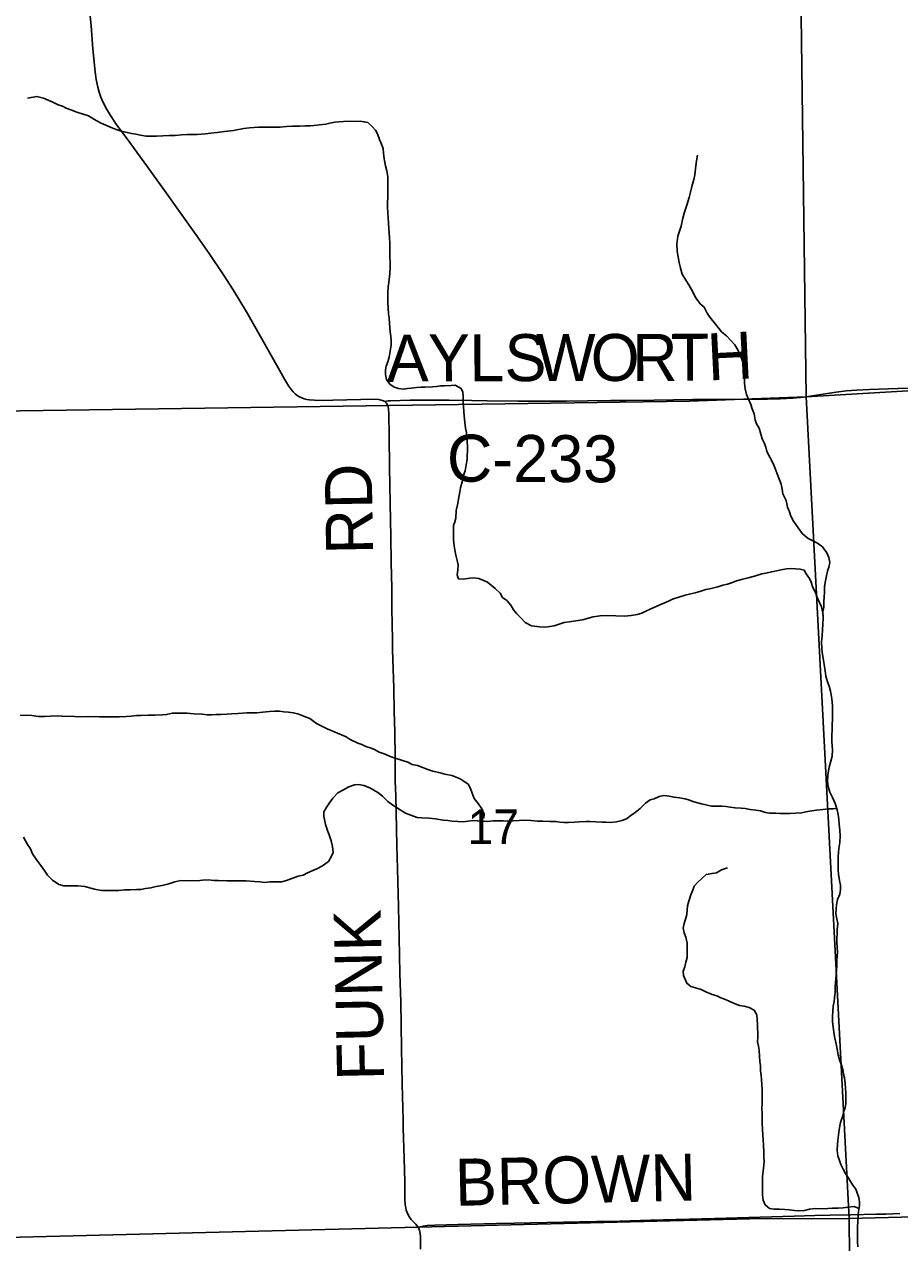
# Model space of a CAD drawing. Extents: x 1985906 to 2360102, y 891258 to 1222054.
# Drawn here: x 2081902 to 2087486, y 977355 to 985131 of the extents above; entities that cross this region are included whole.
import ezdxf

# ---------------------------------------------------------------- set-up
doc = ezdxf.new("R2010")
doc.units = 0
for name, color, linetype in [('GM_X_County_Road', 7, 'Continuous'), ('GM_X_County_Road_Text', 7, 'Continuous'), ('GM_X_Minor_River', 7, 'Continuous'), ('GM_X_Section', 7, 'Continuous'), ('GM_X_Section_Text', 7, 'Continuous'), ('GM_X_Township_Road', 7, 'Continuous'), ('GM_X_Township_Road_Text', 7, 'Continuous')]:
    doc.layers.add(name, color=color, linetype=linetype)

msp = doc.modelspace()

# ---------------------------------------------------------------- linework, layer by layer
at = {"layer": 'GM_X_County_Road'}
for points in [[(2084201.4, 982723), (2084193.3, 982727.4), (2084179.3, 982733), (2084163.9, 982736.4), (2084131.6, 982738.5), (2084049.5, 982737), (2083869.4, 982731.1), (2083803.2, 982729.7), (2083753.8, 982731.1), (2083720.6, 982734), (2083704.2, 982736.8), (2083688, 982740.9), (2083672.2, 982746.6), (2083657.1, 982753.9), (2083642.8, 982762.7), (2083629.6, 982773.1), (2083617.6, 982784.7), (2083606.6, 982797.3), (2083587.3, 982824.3), (2083561.9, 982866.8), (2083529.5, 982924), (2083409.4, 983138.8), (2083319.4, 983295.1), (2083234.8, 983435.5), (2083173.1, 983532.1), (2083081, 983667.9), (2082996.3, 983788.8), (2082796.1, 984069.4), (2082681.3, 984229.4), (2082575.7, 984375.7), (2082487.4, 984494.3), (2082450.8, 984549), (2082425.4, 984591.6), (2082402.8, 984635.7), (2082389.9, 984666.1), (2082379.1, 984697.4), (2082370.3, 984729.3), (2082360.3, 984777.8), (2082353.4, 984826.8), (2082339.9, 984973.9), (2082327.7, 985121.1), (2082314.6, 985268.1)], [(2084201.4, 982723), (2084213.1, 982725.9), (2084223.4, 982727.6), (2084238.8, 982728.8), (2084363.4, 982733), (2084609.5, 982732.8), (2084757.2, 982729.6), (2084855.5, 982728.1), (2085051.9, 982725.8), (2085133.9, 982724.8), (2085265.1, 982724.7), (2085363.5, 982725.4), (2085493.8, 982727), (2085641.7, 982729.2), (2085740, 982730.4), (2085920.5, 982732), (2086166.6, 982735.9), (2086363.4, 982736.6), (2086560.3, 982738.3), (2086642.3, 982739.2), (2086724, 982741), (2086805.4, 982745), (2086854.1, 982749.4), (2086902.7, 982756), (2086983.3, 982769.3), (2087080.5, 982783.8), (2087145.9, 982790.7), (2087211.4, 982795.1), (2087293.4, 982799.3), (2087473.6, 982805.7), (2087555.6, 982808.2)], [(2084414.3, 977451.2), (2084409.8, 977459), (2084398.7, 977472.5), (2084380.7, 977491), (2084369.8, 977503.5), (2084359.7, 977517), (2084350.9, 977531.5), (2084343.7, 977546.7), (2084338.4, 977562.7), (2084334.7, 977579), (2084332.3, 977595.6), (2084330.3, 977628.8), (2084328.8, 977743.9), (2084324.6, 977891.5), (2084319.7, 978088.1), (2084318.3, 978137.3), (2084311.7, 978366.9), (2084307.9, 978596.7), (2084303.1, 978892), (2084298.1, 979072.5), (2084293, 979302.1), (2084288.1, 979499), (2084284.2, 979662.9), (2084278.9, 979892.6), (2084276.1, 979990.9), (2084274.2, 980105.7), (2084272.2, 980204.1), (2084268.5, 980302.6), (2084267.6, 980450.4), (2084265.8, 980614.4), (2084262, 980745.6), (2084258.4, 980893.1), (2084251.2, 981138.8), (2084249.8, 981204.4), (2084247, 981401.2), (2084246, 981532.5), (2084243.1, 981696.5), (2084240.1, 981860.6), (2084236.4, 982073.9), (2084231.9, 982303.6), (2084229.1, 982500.5), (2084227.3, 982648.2), (2084225.6, 982671.1), (2084224.2, 982679.4), (2084222.7, 982687.4), (2084220.2, 982696.8), (2084216.4, 982705.6), (2084211.7, 982712.9), (2084205.6, 982719.4), (2084201.4, 982723)], [(2084429.7, 977312.3), (2084429.7, 977376.9), (2084428.9, 977396), (2084427.4, 977411.2), (2084424.1, 977427.1), (2084417.8, 977444.6), (2084414.3, 977451.2)]]:
    msp.add_lwpolyline(points, dxfattribs=at)
at = {"layer": 'GM_X_Minor_River'}
for points in [[(2081921.8, 984659.3), (2081982.2, 984671.3), (2082024.6, 984659.2), (2082054.8, 984647.1), (2082083.1, 984633.1), (2082117.4, 984617), (2082145.6, 984608.9), (2082169.8, 984596.9), (2082198, 984584.8), (2082236.4, 984570.7), (2082276.7, 984556.7), (2082311, 984546.6), (2082361.4, 984516.5), (2082391.7, 984500.4), (2082421.9, 984486.3), (2082456.2, 984472.2), (2082488.5, 984460.2), (2082520.8, 984450.1), (2082585.3, 984434), (2082613.5, 984430), (2082643.7, 984423.9), (2082680, 984417.9), (2082744.5, 984417.9), (2082825.1, 984421.8), (2082865.4, 984421.8), (2082905.7, 984425.8), (2082941.9, 984427.8), (2083004.4, 984427.8), (2083030.6, 984429.7), (2083058.8, 984431.7), (2083091, 984435.7), (2083131.3, 984439.7), (2083179.7, 984447.7), (2083236.1, 984453.7), (2083302.5, 984465.7), (2083338.8, 984469.7), (2083395.2, 984473.7), (2083534.2, 984473.6), (2083574.5, 984479.6), (2083612.8, 984481.6), (2083657.1, 984481.6), (2083693.4, 984483.6), (2083725.6, 984483.6), (2083749.8, 984485.6), (2083784.1, 984489.6), (2083824.4, 984493.5), (2083850.5, 984499.6), (2083882.8, 984505.6), (2083908.9, 984509.6), (2083937.2, 984511.6), (2083985.5, 984513.5), (2084017.7, 984511.5), (2084043.9, 984513.5), (2084068.1, 984509.5), (2084094.3, 984503.4), (2084120.6, 984479.3), (2084142.8, 984455.2), (2084155, 984431.1), (2084167.1, 984395), (2084181.3, 984366.8), (2084191.4, 984338.7), (2084193.5, 984308.6), (2084197.6, 984272.5), (2084205.8, 984228.3), (2084213.9, 984196.2), (2084220.1, 984158), (2084220.2, 984095.8), (2084220.3, 984065.7), (2084220.4, 984029.5), (2084218.5, 983989.4), (2084218.5, 983965.3), (2084220.6, 983923.1), (2084222.7, 983899), (2084224.8, 983858.9), (2084231.1, 983768.5), (2084233.2, 983734.4), (2084233.4, 983644), (2084235.5, 983615.9), (2084235.6, 983575.8), (2084233.6, 983539.6), (2084227.7, 983483.4), (2084223.8, 983455.3), (2084221.8, 983419.2), (2084221.9, 983389), (2084220, 983354.9), (2084222.1, 983318.8), (2084226.2, 983282.6), (2084230.3, 983258.5), (2084232.4, 983222.4), (2084234.4, 983194.3), (2084236.5, 983168.2), (2084240.6, 983138.1), (2084242.7, 983109.9), (2084242.8, 983083.8), (2084236.8, 983045.7), (2084228.8, 983005.6), (2084220.8, 982977.4), (2084210.8, 982949.3), (2084206.9, 982925.3), (2084206.9, 982895.1), (2084213.1, 982863)], [(2086997.1, 981345.5), (2086995.2, 981381.7), (2087001.2, 981411.8), (2087003.1, 981441.9), (2087005.1, 981478.1), (2087007, 981504.2), (2087006.9, 981542.3), (2087012.9, 981578.4), (2087018.9, 981610.6), (2087024.9, 981640.7), (2087034.9, 981666.8), (2087040.8, 981696.9), (2087034.7, 981729), (2087020.5, 981757.1), (2086994.3, 981795.3), (2086962, 981819.4), (2086931.7, 981833.5), (2086901.4, 981849.5), (2086867.1, 981879.7), (2086838.8, 981917.8), (2086808.5, 981960), (2086792.3, 981992.2), (2086782.2, 982020.3), (2086770, 982048.4), (2086761.8, 982092.6), (2086741.6, 982134.8), (2086735.5, 982164.9), (2086729.4, 982197), (2086719.2, 982223.1), (2086705, 982261.3), (2086690.8, 982295.4), (2086678.7, 982327.5), (2086658.4, 982367.7), (2086638.2, 982403.8), (2086632.1, 982432), (2086621.9, 982460.1), (2086609.8, 982486.2), (2086599.7, 982514.3), (2086589.5, 982552.4), (2086573.3, 982580.6), (2086565.2, 982606.7), (2086557, 982644.8), (2086544.9, 982676.9), (2086536.7, 982705.1), (2086520.5, 982743.2), (2086508.4, 982769.3), (2086500.2, 982803.5), (2086496.1, 982841.6), (2086496, 982883.8), (2086493.9, 982923.9), (2086487.8, 982968.1), (2086479.6, 982994.2), (2086465.5, 983022.3), (2086455.3, 983048.4), (2086435.1, 983084.6), (2086410.9, 983110.7), (2086380.6, 983142.8), (2086350.3, 983169), (2086311.9, 983217.2), (2086275.5, 983261.4), (2086257.3, 983287.5), (2086239.1, 983325.6), (2086212.8, 983347.7), (2086186.5, 983385.9), (2086158.2, 983438.1), (2086142, 983468.2), (2086121.8, 983498.4), (2086099.5, 983536.5), (2086087.4, 983574.7), (2086079.2, 983610.8), (2086071, 983657), (2086067, 983683.1), (2086064.8, 983727.3), (2086070.8, 983779.5), (2086092.8, 983843.7), (2086102.7, 983893.9), (2086110.7, 983926), (2086128.7, 983976.2), (2086142.7, 984026.4), (2086150.7, 984060.5), (2086160.7, 984096.7), (2086172.7, 984140.8), (2086178.6, 984170.9), (2086186.6, 984227.2), (2086190.5, 984259.3), (2086196.5, 984295.4)], [(2084213.1, 982863), (2084233.3, 982834.9), (2084261.5, 982814.8), (2084289.8, 982806.8), (2084320, 982802.7), (2084346.2, 982806.7), (2084370.4, 982808.7), (2084404.6, 982812.7), (2084430.8, 982814.7), (2084457, 982814.7), (2084505.3, 982816.7), (2084531.5, 982818.7), (2084557.7, 982822.7), (2084581.9, 982822.6), (2084624.2, 982826.6), (2084650.4, 982828.6), (2084688.7, 982806.5), (2084698.9, 982782.4), (2084700.9, 982756.3), (2084701, 982724.2), (2084705.2, 982659.9), (2084707.3, 982631.8), (2084711.4, 982591.7), (2084715.5, 982553.5), (2084723.7, 982525.4), (2084725.7, 982497.3), (2084727.8, 982463.2), (2084729.9, 982439.1), (2084730, 982411), (2084728, 982376.8), (2084726.1, 982352.8), (2084720.1, 982318.6), (2084714.1, 982280.5), (2084702.1, 982246.3), (2084694.2, 982210.2), (2084684.2, 982172.1), (2084680.2, 982148), (2084676.2, 982123.9), (2084666.3, 982063.7), (2084656.3, 982027.5), (2084654.4, 981979.3), (2084648.4, 981955.2), (2084640.4, 981931.2), (2084640.6, 981840.8), (2084644.7, 981802.7), (2084648.8, 981776.6), (2084655, 981742.4), (2084663.1, 981708.3), (2084669.2, 981682.2), (2084667.3, 981648), (2084663.3, 981617.9), (2084671.4, 981591.8), (2084703.7, 981589.8), (2084744, 981595.8), (2084768.1, 981597.8), (2084800.4, 981593.8), (2084826.6, 981583.7), (2084856.9, 981569.7), (2084905.3, 981529.5), (2084937.6, 981499.3), (2084951.8, 981473.2), (2084980, 981453.1), (2085006.3, 981423), (2085022.5, 981394.9), (2085044.7, 981368.8), (2085069, 981342.7), (2085097.2, 981312.5), (2085137.6, 981292.4), (2085188, 981286.4), (2085218.2, 981284.3), (2085242.4, 981286.3), (2085282.7, 981292.3), (2085312.9, 981302.3), (2085345.1, 981312.4), (2085377.3, 981316.4), (2085461.9, 981330.4), (2085530.4, 981348.4), (2085574.7, 981356.4), (2085623.1, 981358.4), (2085675.4, 981356.4), (2085729.9, 981354.3), (2085774.2, 981358.3), (2085810.4, 981364.3), (2085840.6, 981372.3), (2085866.8, 981386.4), (2085895, 981398.4), (2085955.4, 981426.5), (2085981.5, 981436.5), (2086011.7, 981448.5), (2086035.9, 981462.6), (2086076.2, 981474.6), (2086118.5, 981486.6), (2086144.6, 981494.6), (2086180.9, 981502.6), (2086217.1, 981512.7), (2086249.3, 981522.7), (2086275.5, 981528.7), (2086325.9, 981540.7), (2086358.1, 981550.7), (2086388.3, 981558.7), (2086418.5, 981568.8)], [(2086418.5, 981568.8), (2086444.7, 981578.8), (2086484.9, 981588.8), (2086519.2, 981598.8), (2086559.4, 981608.8), (2086605.8, 981622.8), (2086642, 981630.9), (2086670.2, 981636.9), (2086730.6, 981648.9), (2086764.9, 981654.9), (2086797.1, 981656.9), (2086821.3, 981654.8), (2086851.5, 981652.8), (2086877.7, 981646.8), (2086889.9, 981622.7), (2086910.1, 981594.6), (2086922.2, 981570.5), (2086932.4, 981536.3), (2086948.6, 981504.2), (2086956.7, 981478.1), (2086972.9, 981446), (2086987.1, 981413.8), (2086995.2, 981375.7), (2086997.3, 981341.5), (2086995.4, 981301.4), (2086991.6, 981229.1), (2086987.6, 981186.9), (2086989.7, 981146.8), (2086991.8, 981120.7), (2087000, 981072.5), (2087006.1, 981030.3), (2087010.2, 981004.2), (2087014.3, 980970.1), (2087026.5, 980933.9), (2087036.6, 980905.8), (2087044.8, 980875.7), (2087050.9, 980841.6), (2087055, 980807.4), (2087057.1, 980779.3), (2087057.3, 980697), (2087055.4, 980658.9), (2087055.4, 980634.8), (2087053.5, 980588.6), (2087053.6, 980552.5), (2087057.7, 980500.3), (2087055.8, 980460.1), (2087045.8, 980428), (2087035.8, 980389.8), (2087031.9, 980365.8), (2087027.9, 980337.7), (2087026, 980297.5), (2087030.1, 980265.4), (2087040.2, 980229.2), (2087056.4, 980197.1), (2087074.6, 980156.9), (2087086.8, 980116.8), (2087092.9, 980086.7), (2087097.1, 980056.5), (2087099.1, 980026.4), (2087103.3, 979988.3), (2087105.4, 979952.1), (2087103.4, 979907.9), (2087097.5, 979869.8), (2087093.6, 979819.6), (2087093.8, 979731.3), (2087095.8, 979707.2), (2087102, 979667), (2087108.1, 979636.9), (2087108.2, 979608.8), (2087104.2, 979578.7), (2087090.2, 979544.6), (2087082.2, 979510.4), (2087080.2, 979486.3), (2087078.3, 979454.2), (2087084.4, 979422.1), (2087090.5, 979392), (2087086.6, 979353.8), (2087086.7, 979325.7), (2087084.7, 979299.6), (2087084.8, 979271.5), (2087086.9, 979239.4), (2087088.9, 979209.3), (2087087, 979185.2), (2087085, 979155.1), (2087085.1, 979120.9), (2087083.2, 979094.8), (2087081.2, 979064.7), (2087079.3, 979038.6), (2087075.3, 978990.4), (2087073.4, 978954.3), (2087069.5, 978918.2), (2087067.5, 978894.1), (2087061.5, 978864), (2087059.6, 978831.8), (2087057.7, 978797.7), (2087057.7, 978765.6), (2087061.8, 978729.4), (2087068, 978683.3), (2087072.1, 978659.2), (2087080.2, 978623), (2087086.3, 978590.9)], [(2081876.6, 980720), (2081912.9, 980722), (2081949.2, 980720), (2081991.5, 980714), (2082033.8, 980713.9), (2082070.1, 980715.9), (2082112.4, 980717.9), (2082140.6, 980715.9), (2082223.2, 980713.8), (2082261.5, 980711.8), (2082320, 980713.8), (2082382.4, 980711.7), (2082507.4, 980711.7), (2082553.7, 980713.7), (2082583.9, 980715.6), (2082618.2, 980719.6), (2082644.4, 980719.6), (2082692.7, 980721.6), (2082735, 980721.6), (2082783.4, 980723.6), (2082809.6, 980725.5), (2082845.8, 980733.6), (2082872, 980733.5), (2082940.5, 980733.5), (2082982.8, 980729.5), (2083037.3, 980727.4), (2083067.5, 980723.4), (2083095.7, 980723.4), (2083123.9, 980725.4), (2083156.2, 980725.4), (2083194.4, 980727.3), (2083224.6, 980729.3), (2083264.9, 980733.3), (2083321.4, 980737.3), (2083385.8, 980737.3), (2083424.1, 980741.3), (2083466.4, 980745.3), (2083500.7, 980747.2), (2083530.9, 980747.2), (2083557.1, 980743.2), (2083587.3, 980741.2), (2083617.6, 980737.1), (2083645.8, 980731.1), (2083690.1, 980713), (2083722.4, 980700.9), (2083766.8, 980668.8), (2083833.4, 980634.6), (2083885.8, 980612.5), (2083954.4, 980584.4), (2083980.6, 980566.3), (2084029.1, 980542.2), (2084055.3, 980534.1), (2084081.5, 980522), (2084107.7, 980514), (2084136, 980501.9), (2084166.2, 980485.9), (2084204.5, 980471.8), (2084236.8, 980457.7), (2084275.1, 980445.6), (2084347.7, 980421.5), (2084376, 980407.4), (2084410.2, 980399.4), (2084476.8, 980375.3), (2084507, 980365.2), (2084555.4, 980353.1), (2084583.7, 980345.1), (2084630, 980337), (2084678.4, 980316.9), (2084706.7, 980300.8), (2084732.9, 980280.8), (2084749.1, 980252.6), (2084759.2, 980224.5), (2084771.4, 980190.4), (2084797.7, 980158.2), (2084819.9, 980124.1), (2084836.1, 980090), (2084834.2, 980063.8)], [(2087084, 980126.1), (2087062.6, 980124.8), (2087032.4, 980122.8), (2086996.2, 980118.8), (2086955.9, 980114.8), (2086925.6, 980110.8), (2086887.4, 980104.8), (2086859.2, 980098.8), (2086820.9, 980096.8), (2086784.6, 980094.9), (2086722.2, 980094.9), (2086696, 980096.9), (2086655.7, 980096.9), (2086629.5, 980101), (2086599.2, 980111), (2086569, 980115), (2086532.7, 980119.1), (2086500.4, 980125.1), (2086474.2, 980127.2), (2086436, 980129.2), (2086403.7, 980135.2), (2086377.5, 980139.3), (2086351.3, 980141.3), (2086284.8, 980141.3), (2086248.5, 980149.4), (2086222.3, 980155.4), (2086173.9, 980169.5), (2086145.7, 980179.5), (2086117.4, 980187.6), (2086081.2, 980193.7), (2086046.9, 980197.7), (2086014.6, 980205.7), (2085982.4, 980209.8), (2085952.2, 980201.7), (2085920, 980187.7), (2085893.8, 980181.7), (2085863.6, 980159.6), (2085831.5, 980125.5), (2085799.3, 980099.4), (2085771.1, 980081.4), (2085743, 980059.3), (2085712.7, 980049.3), (2085680.5, 980041.3), (2085640.2, 980037.3), (2085612, 980039.3), (2085585.8, 980039.3), (2085547.5, 980041.4), (2085511.3, 980043.4), (2085485.1, 980043.4), (2085440.7, 980041.4), (2085412.5, 980039.4), (2085374.3, 980037.4), (2085344, 980037.5), (2085317.8, 980039.5), (2085291.6, 980043.5), (2085253.3, 980043.5), (2085209, 980045.6), (2085174.7, 980045.6), (2085132.4, 980049.6), (2085094.1, 980051.7), (2084985.3, 980045.7), (2084957.1, 980047.7), (2084892.6, 980047.8), (2084858.4, 980043.8), (2084830.2, 980045.8), (2084793.9, 980047.8), (2084767.7, 980049.8), (2084731.4, 980045.8), (2084701.2, 980041.8), (2084667, 980043.9), (2084630.7, 980045.9), (2084604.5, 980049.9), (2084574.3, 980052), (2084525.9, 980060), (2084485.6, 980064.1), (2084437.2, 980066.1), (2084407, 980068.1), (2084366.6, 980084.2), (2084334.4, 980096.3), (2084300.1, 980118.4), (2084253.7, 980146.5), (2084221.4, 980170.6), (2084187, 980204.8), (2084156.7, 980228.9), (2084106.3, 980257), (2084068, 980273.1), (2084035.7, 980279.1), (2084007.5, 980277.2), (2083971.3, 980265.1), (2083933, 980243.1), (2083902.9, 980225), (2083870.7, 980190.9), (2083848.6, 980162.8), (2083828.5, 980130.7), (2083812.5, 980104.6), (2083812.5, 980076.5), (2083822.7, 980024.3), (2083836.9, 979986.1), (2083849.1, 979952), (2083859.2, 979919.8), (2083867.4, 979883.7)], [(2083867.4, 979883.7), (2083871.5, 979845.6), (2083857.5, 979813.4), (2083841.4, 979787.3), (2083803.2, 979759.3), (2083769, 979741.2), (2083742.8, 979731.2), (2083708.6, 979715.2), (2083680.4, 979701.1), (2083648.2, 979693.1), (2083607.9, 979679.1), (2083573.7, 979667), (2083543.5, 979657), (2083468.9, 979657.1), (2083434.7, 979653.1), (2083404.5, 979657.1), (2083370.2, 979659.1), (2083317.8, 979663.2), (2083269.4, 979665.2), (2083192.9, 979665.2), (2083140.5, 979667.3), (2083110.2, 979667.3), (2083078, 979671.3), (2083039.7, 979669.3), (2083005.5, 979665.3), (2082900.7, 979665.4), (2082862.4, 979657.4), (2082824.2, 979645.4), (2082781.9, 979635.4), (2082743.6, 979627.4), (2082709.4, 979619.3), (2082675.1, 979615.3), (2082644.9, 979609.3), (2082618.7, 979609.4), (2082576.4, 979607.4), (2082540.1, 979607.4), (2082505.9, 979603.4), (2082395.1, 979603.5), (2082350.7, 979611.5), (2082288.2, 979627.6), (2082243.9, 979631.7), (2082155.2, 979631.7), (2082123, 979639.8), (2082082.6, 979667.9), (2082050.3, 979700), (2082032.1, 979726.1), (2082007.8, 979762.3), (2081981.5, 979796.4), (2081955.3, 979836.6), (2081941.1, 979868.7), (2081922.9, 979896.8), (2081896.6, 979943)], [(2087226.9, 977574.1), (2087221.7, 977574.9), (2087195.5, 977585), (2087155.2, 977581), (2087125, 977577), (2087092.7, 977575), (2087058.5, 977575), (2087028.3, 977573), (2086994, 977571), (2086947.7, 977573.1), (2086911.4, 977569.1), (2086879.2, 977561.1), (2086842.9, 977557.1), (2086814.7, 977561.1), (2086780.4, 977565.1), (2086754.2, 977567.2), (2086720, 977569.2), (2086685.7, 977569.2), (2086655.5, 977573.2), (2086627.2, 977597.3), (2086615.1, 977625.5), (2086611, 977659.6), (2086610.7, 977774), (2086616.6, 977830.2), (2086620.5, 977870.4), (2086618.4, 977902.5), (2086618.4, 977934.7), (2086616.3, 977974.8), (2086616.2, 978012.9), (2086612.1, 978041.1), (2086610, 978079.2), (2086607.9, 978115.3), (2086607.8, 978147.5), (2086609.7, 978181.6), (2086607.7, 978211.7), (2086609.6, 978243.8), (2086609.4, 978334.2), (2086607.3, 978364.3), (2086605.2, 978396.4), (2086603.1, 978422.5), (2086599, 978450.7), (2086599, 978482.8), (2086594.9, 978510.9), (2086592.8, 978545), (2086588.7, 978583.2), (2086584.6, 978609.3), (2086578.5, 978637.4), (2086580.4, 978665.5), (2086580.3, 978695.6), (2086578.3, 978721.7), (2086578.2, 978747.8), (2086576.1, 978779.9), (2086574, 978810), (2086557.8, 978838.2), (2086525.6, 978856.2), (2086493.3, 978864.3), (2086465.1, 978868.3), (2086436.8, 978878.4), (2086402.5, 978894.5), (2086374.3, 978906.5), (2086346.1, 978916.6), (2086319.9, 978930.7), (2086289.6, 978938.7), (2086249.3, 978954.8), (2086219, 978970.9), (2086182.7, 978980.9), (2086154.5, 978989), (2086128.2, 979011.1), (2086108, 979059.3), (2086103.9, 979087.4), (2086115.9, 979115.5), (2086121.9, 979145.6), (2086129.9, 979175.7), (2086129.7, 979266), (2086121.5, 979304.2), (2086111.4, 979332.3), (2086105.3, 979362.4), (2086111.2, 979392.5), (2086119.2, 979418.6), (2086127.2, 979448.8), (2086131.2, 979476.8), (2086133.1, 979505), (2086141.1, 979535.1), (2086153.1, 979575.2), (2086165.1, 979601.3), (2086175.2, 979629.4), (2086199.3, 979655.5), (2086251.6, 979703.7), (2086289.8, 979711.7), (2086318, 979715.7), (2086350.2, 979733.7), (2086388.5, 979747.8)], [(2087086.3, 978590.9), (2087094.5, 978552.8), (2087104.7, 978514.6), (2087114.8, 978488.5), (2087122.9, 978460.4), (2087127, 978430.3), (2087133.1, 978406.2), (2087137.2, 978370), (2087141.3, 978339.9), (2087143.4, 978307.8), (2087143.5, 978271.6), (2087141.6, 978241.5), (2087137.6, 978217.4), (2087129.6, 978193.3), (2087123.6, 978165.2), (2087107.6, 978121.1), (2087099.6, 978076.9), (2087095.7, 978040.8), (2087091.7, 978006.7), (2087089.8, 977982.6), (2087087.9, 977942.4), (2087092, 977908.3), (2087102.1, 977880.2), (2087110.2, 977854.1), (2087126.4, 977823.9), (2087140.6, 977795.8), (2087156.8, 977769.7), (2087172.9, 977745.6), (2087187.1, 977721.5), (2087205.3, 977695.4), (2087225.6, 977643.2), (2087229.7, 977615.1), (2087229.7, 977591), (2087223.8, 977554.8), (2087221.8, 977528.8), (2087219.9, 977490.6), (2087215.9, 977454.5), (2087216.1, 977362.1), (2087218.2, 977328)]]:
    msp.add_lwpolyline(points, dxfattribs=at)
at = {"layer": 'GM_X_Section'}
for points in [[(2086819, 988102.7), (2092434.9, 988320.1), (2092461, 982961.6), (2089745.7, 982922.4), (2086889, 982754.4)], [(2081474.6, 988006.6), (2086819, 988102.7), (2086889, 982754.4), (2086144.8, 982726.8), (2081578.7, 982660.5)], [(2086889, 982754.4), (2089745.7, 982922.4), (2092461, 982961.6), (2092504.9, 977615.1), (2089829.7, 977576.1), (2087164.7, 977509.1)], [(2081578.7, 982660.5), (2086144.8, 982726.8), (2086889, 982754.4), (2087164.7, 977509.1), (2086530.3, 977506), (2081702.4, 977386.5)], [(2087164.7, 977509.1), (2089829.7, 977576.1), (2092504.9, 977615.1), (2092561.1, 972236.7), (2087210.6, 972175.8)], [(2081702.4, 977386.5), (2086530.3, 977506), (2087164.7, 977509.1), (2087210.6, 972175.8), (2081764.1, 972104)]]:
    msp.add_lwpolyline(points, close=True, dxfattribs=at)
at = {"layer": 'GM_X_Township_Road'}
msp.add_lwpolyline([(2084414.3, 977451.2), (2084429.4, 977455.6), (2084446.7, 977459.9), (2084459.9, 977462.3), (2084471.9, 977463.7), (2084520.8, 977466.7), (2084668.3, 977470.9), (2084750.1, 977473.3), (2084913.7, 977477), (2085028.3, 977479.5), (2085339.8, 977485.6), (2085552.8, 977490.9), (2085700.5, 977492.7), (2085897.2, 977498), (2086061.1, 977501.8), (2086306.9, 977508.5), (2086811.9, 977524), (2086945.6, 977527.2), (2087039.4, 977529.5), (2087174.8, 977531.5), (2087338.9, 977535.7), (2087398, 977537.2), (2087487.2, 977540)], dxfattribs=at)

# ---------------------------------------------------------------- texts
at = {"layer": 'GM_X_County_Road_Text'}
for s, rotation, p in [('O', 0.12203, (2085515.5, 982854.3)), ('H', 2.81231, (2086265.7, 982857.4)), ('A', 0.9854, (2084214.4, 982847.4)), ('Y', 0.17485, (2084477.2, 982851.9)), ('L', 0.12214, (2084741.1, 982852.7)), ('S', 0.12369, (2084965.6, 982853.2)), ('W', 0.12309, (2085167.9, 982853.6)), ('R', 0.12449, (2085779.6, 982854.9)), ('T', 0.39716, (2086027.5, 982855.4)), ('C-233', 359.72385, (2084597.1, 982212.6)), ('RD', 90.98581, (2084127.5, 981750.1)), ('FUNK', 91.20609, (2084197.7, 978392.3))]:
    msp.add_text(s, height=300, rotation=rotation, dxfattribs=at).set_placement(p)
at = {"layer": 'GM_X_Section_Text'}
msp.add_text('17', height=221, rotation=0.00001, dxfattribs=at).set_placement((2084729.4, 979898.9))
at = {"layer": 'GM_X_Township_Road_Text'}
msp.add_text('BROWN', height=300, rotation=1.28953, dxfattribs=at).set_placement((2084652.2, 977589.4))

doc.saveas('drawing.dxf')
